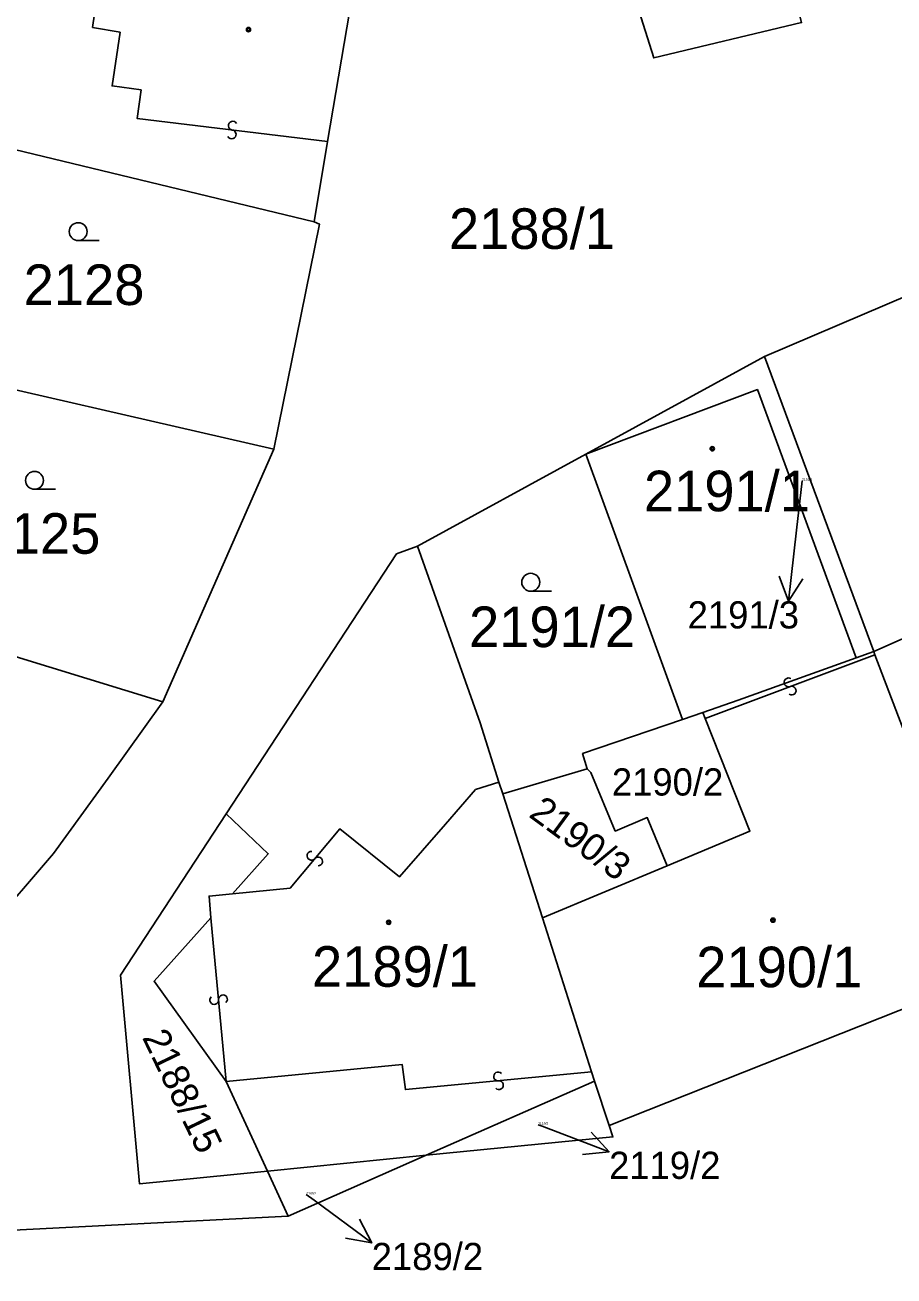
# Model space of a CAD drawing. Extents: x -596024 to -594475, y -1163820 to -1161957.
# Drawn here: x -595981.6 to -595945.3, y -1163000.7 to -1162948.3 of the extents above; entities that cross this region are included whole.
import ezdxf

# ---------------------------------------------------------------- set-up
doc = ezdxf.new("R2010")
doc.units = 0
for name, color, linetype in [('Level 1', 7, 'Continuous'), ('Level 13', 7, 'Continuous'), ('Level 3', 7, 'Continuous'), ('Level 4', 7, 'Continuous'), ('Level 5', 7, 'Continuous'), ('Level 57', 7, 'Continuous'), ('Level 60', 7, 'Continuous')]:
    doc.layers.add(name, color=color, linetype=linetype)

msp = doc.modelspace()

# ---------------------------------------------------------------- linework, layer by layer
at = {"layer": 'Level 1'}
for points in [[(-595968.97, -1162953.21), (-595967.57, -1162944.98)], [(-595956.2, -1162946.87), (-595955.31, -1162949.71), (-595949.12, -1162948.23)], [(-595969.53, -1162956.57), (-595989.38, -1162951.78)], [(-595969.53, -1162956.57), (-595968.97, -1162953.21)], [(-595950.67, -1162962.21), (-595942.49, -1162958.73), (-595931.21, -1162955.02)], [(-595971.22, -1162966.1), (-595969.31, -1162956.67), (-595969.53, -1162956.57)], [(-595971.22, -1162966.1), (-595986.91, -1162962.5)], [(-595958.16, -1162966.31), (-595950.67, -1162962.21)], [(-595950.67, -1162962.21), (-595946.1, -1162974.57)], [(-595958.16, -1162966.31), (-595950.97, -1162963.6), (-595946.84, -1162974.84)], [(-595975.86, -1162976.69), (-595971.22, -1162966.1)], [(-595965.2, -1162970.16), (-595958.16, -1162966.31)], [(-595954.11, -1162977.42), (-595958.16, -1162966.31)], [(-595934.03, -1162966.89), (-595938.96, -1162968.52), (-595938.13, -1162971.04), (-595946.1, -1162974.57)], [(-595965.2, -1162970.16), (-595966.08, -1162970.49), (-595973.22, -1162981.38)], [(-595965.2, -1162970.16), (-595962.58, -1162977.57), (-595961.79, -1162980.05)], [(-595975.86, -1162976.69), (-595990.39, -1162972.23)], [(-595946.1, -1162974.57), (-595946.84, -1162974.84)], [(-595946.1, -1162974.57), (-595946.05, -1162974.71)], [(-595946.05, -1162974.71), (-595943.52, -1162981.33)], [(-595953.25, -1162977.13), (-595951.77, -1162976.62), (-595946.84, -1162974.84)], [(-595983.23, -1162986.27), (-595980.45, -1162983.04), (-595978.15, -1162979.88), (-595975.86, -1162976.69)], [(-595953.25, -1162977.13), (-595954.11, -1162977.42)], [(-595953.15, -1162977.38), (-595953.25, -1162977.13)], [(-595954.11, -1162977.42), (-595958.29, -1162978.85), (-595958.1, -1162979.49)], [(-595954.75, -1162983.55), (-595951.28, -1162982.1), (-595953.15, -1162977.38)], [(-595958.1, -1162979.49), (-595961.63, -1162980.54)], [(-595954.75, -1162983.55), (-595955.58, -1162981.53), (-595956.92, -1162982.1), (-595957.94, -1162979.65), (-595958.1, -1162979.49)], [(-595961.79, -1162980.05), (-595961.63, -1162980.54)], [(-595959.97, -1162985.73), (-595961.63, -1162980.54)], [(-595971.49, -1162996.34), (-595976.85, -1162996.87), (-595977.64, -1162988.13), (-595973.22, -1162981.38)], [(-595973.22, -1162981.38), (-595971.45, -1162983.05), (-595972.95, -1162984.72)], [(-595959.97, -1162985.73), (-595954.75, -1162983.55)], [(-595972.95, -1162984.72), (-595973.93, -1162984.82), (-595973.85, -1162985.73)], [(-595973.85, -1162985.73), (-595976.23, -1162988.39), (-595973.21, -1162992.59)], [(-595957.92, -1162992.18), (-595959.97, -1162985.73)], [(-595957.18, -1162994.43), (-595940.98, -1162988.01)], [(-595957.92, -1162992.18), (-595957.79, -1162992.58)], [(-595971.49, -1162996.34), (-595973.21, -1162992.59)], [(-595964.84, -1162995.68), (-595957.79, -1162992.58)], [(-595957.79, -1162992.58), (-595957.18, -1162994.43)], [(-595964.84, -1162995.68), (-595957.02, -1162994.91), (-595957.18, -1162994.43)], [(-595964.84, -1162995.68), (-595971.49, -1162996.34)], [(-595970.62, -1162998.23), (-595964.84, -1162995.68)], [(-595970.62, -1162998.23), (-595971.49, -1162996.34)], [(-595970.62, -1162998.23), (-595993.35, -1162999.39)]]:
    msp.add_lwpolyline(points, dxfattribs=at)
at = {"layer": 'Level 13'}
for centre, start, end in [((-595972.937, -1162952.547), 30.29, 262.88), ((-595972.984, -1162952.913), 210.5045, 82.6024), ((-595949.663, -1162975.867), 57.9818, 290.0798), ((-595949.536, -1162976.213), 237.7674, 110.3574), ((-595969.641, -1162983.131), 87.1714, 319.7614), ((-595969.36, -1162983.37), 267.3858, 139.4838), ((-595973.714, -1162989.175), 132.7027, 4.8007), ((-595973.347, -1162989.144), 312.4882, 185.0782), ((-595961.826, -1162992.376), 42.8721, 274.9701), ((-595961.793, -1162992.743), 222.6576, 95.2476)]:
    msp.add_arc(centre, 0.184, start, end, dxfattribs=at)
at = {"layer": 'Level 3'}
for points in [[(-595968.97, -1162953.21), (-595976.94, -1162952.25), (-595976.78, -1162951.05), (-595977.99, -1162950.88), (-595977.66, -1162948.63), (-595978.81, -1162948.43), (-595978.63, -1162947.18), (-595978.79, -1162947.15), (-595978.24, -1162943.41)], [(-595953.15, -1162977.38), (-595946.05, -1162974.71)], [(-595961.79, -1162980.05), (-595962.77, -1162980.35), (-595964.03, -1162981.81), (-595965.96, -1162984.02), (-595968.46, -1162982.01), (-595970.54, -1162984.49), (-595972.95, -1162984.72)], [(-595973.21, -1162992.59), (-595973.85, -1162985.73)], [(-595973.21, -1162992.59), (-595965.85, -1162991.87), (-595965.71, -1162992.93), (-595957.92, -1162992.18)]]:
    msp.add_lwpolyline(points, dxfattribs=at)
at = {"layer": 'Level 5'}
for p, q in [((-595979.41, -1162957.36), (-595978.535, -1162957.36)), ((-595981.24, -1162967.78), (-595980.365, -1162967.78)), ((-595960.46, -1162972.05), (-595959.585, -1162972.05))]:
    msp.add_line(p, q, dxfattribs=at)
for centre, radius in [((-595972.28, -1162948.52), 0.09), ((-595972.28, -1162948.52), 0.0521), ((-595979.41, -1162956.985), 0.375), ((-595952.86, -1162966.08), 0.09), ((-595952.86, -1162966.08), 0.0521), ((-595981.24, -1162967.405), 0.375), ((-595960.46, -1162971.675), 0.375), ((-595966.41, -1162985.92), 0.09), ((-595966.41, -1162985.92), 0.0521), ((-595950.32, -1162985.83), 0.09), ((-595950.32, -1162985.83), 0.0521)]:
    msp.add_circle(centre, radius, dxfattribs=at)
at = {"layer": 'Level 57'}
for p, q in [((-595949.1, -1162967.42), (-595949.334, -1162969.489)), ((-595949.334, -1162969.489), (-595949.67, -1162972.47)), ((-595960.15, -1162994.4), (-595959.984, -1162994.463)), ((-595959.984, -1162994.463), (-595957.18, -1162995.53)), ((-595969.86, -1162997.32), (-595969.531, -1162997.564)), ((-595969.531, -1162997.564), (-595967.12, -1162999.35))]:
    msp.add_line(p, q, dxfattribs=at)
for points in [[(-595949.061, -1162971.532), (-595949.67, -1162972.47), (-595950.055, -1162971.42)], [(-595957.937, -1162994.707), (-595957.18, -1162995.53), (-595958.293, -1162995.642)], [(-595967.626, -1162998.353), (-595967.12, -1162999.35), (-595968.222, -1162999.156)]]:
    msp.add_lwpolyline(points, dxfattribs=at)
at = {"layer": 'Level 60'}
for points in [[(-595958.99, -1162933.23), (-595959.54, -1162929.94), (-595959.64, -1162928.73), (-595960.71, -1162916.38), (-595954.47, -1162915.56), (-595953.88, -1162923.87), (-595953.69, -1162926.6), (-595953.39, -1162928.83), (-595953.31, -1162929.42), (-595952.98, -1162931.95), (-595953.08, -1162932.3), (-595953.68, -1162935.69), (-595952.71, -1162938.94), (-595950.92, -1162938.63), (-595949.84, -1162945.38), (-595949.12, -1162948.23), (-595955.31, -1162949.71), (-595956.2, -1162946.87)], [(-596009.19, -1162949.12), (-596012.98, -1162948.44), (-596011.05, -1162938.75), (-596007.41, -1162939.32), (-596001.3, -1162940.16), (-595998.35, -1162940.53), (-595996.92, -1162940.71), (-595990.45, -1162941.67), (-595987.96, -1162942), (-595987.61, -1162942.05), (-595978.24, -1162943.41), (-595974.47, -1162943.95), (-595967.57, -1162944.98), (-595968.97, -1162953.21), (-595969.53, -1162956.57), (-595989.38, -1162951.78), (-595989.67, -1162951.71), (-595991.62, -1162951.35), (-595992.41, -1162951.21), (-595994.23, -1162950.96), (-595997.62, -1162950.49), (-595998.08, -1162950.45), (-596000.25, -1162950.27)], [(-595969.31, -1162956.67), (-595971.22, -1162966.1), (-595986.91, -1162962.5), (-595986.37, -1162959.04), (-595990.65, -1162958.26), (-595990.15, -1162955.34), (-595989.85, -1162955.39), (-595989.38, -1162951.78), (-595969.53, -1162956.57)], [(-595950.67, -1162962.21), (-595942.49, -1162958.73), (-595931.21, -1162955.02), (-595929.93, -1162958.74), (-595927.84, -1162964.62), (-595934.03, -1162966.89), (-595938.96, -1162968.52), (-595938.13, -1162971.04), (-595946.1, -1162974.57)], [(-595975.86, -1162976.69), (-595990.39, -1162972.23), (-595992.62, -1162971.72), (-595991.84, -1162968.06), (-595991.58, -1162966.83), (-595987.82, -1162967.36), (-595986.91, -1162962.5), (-595971.22, -1162966.1)], [(-595950.97, -1162963.6), (-595958.16, -1162966.31), (-595950.67, -1162962.21), (-595946.1, -1162974.57), (-595946.84, -1162974.84)], [(-595951.77, -1162976.62), (-595953.25, -1162977.13), (-595954.11, -1162977.42), (-595958.16, -1162966.31), (-595950.97, -1162963.6), (-595946.84, -1162974.84)], [(-595940.18, -1162989.98), (-595940.98, -1162988.01), (-595943.52, -1162981.33), (-595946.05, -1162974.71), (-595946.1, -1162974.57), (-595938.13, -1162971.04), (-595938.96, -1162968.52), (-595934.03, -1162966.89), (-595927.84, -1162964.62), (-595923.34, -1162978.02), (-595921.07, -1162984.8)], [(-595958.16, -1162966.31), (-595954.11, -1162977.42), (-595958.29, -1162978.85), (-595958.1, -1162979.49), (-595961.63, -1162980.54), (-595961.79, -1162980.05), (-595962.58, -1162977.57), (-595965.2, -1162970.16)], [(-595973.93, -1162984.82), (-595972.95, -1162984.72), (-595971.45, -1162983.05), (-595973.22, -1162981.38), (-595966.08, -1162970.49), (-595965.2, -1162970.16), (-595962.58, -1162977.57), (-595961.79, -1162980.05), (-595961.63, -1162980.54), (-595959.97, -1162985.73), (-595957.92, -1162992.18), (-595957.79, -1162992.58), (-595964.84, -1162995.68), (-595971.49, -1162996.34), (-595973.21, -1162992.59), (-595976.23, -1162988.39), (-595973.85, -1162985.73)], [(-595978.15, -1162979.88), (-595980.45, -1162983.04), (-595983.23, -1162986.27), (-595991.9, -1162981.05), (-595991.18, -1162976.32), (-595990.39, -1162972.23), (-595975.86, -1162976.69)], [(-595959.97, -1162985.73), (-595954.75, -1162983.55), (-595951.28, -1162982.1), (-595953.15, -1162977.38), (-595953.25, -1162977.13), (-595951.77, -1162976.62), (-595946.84, -1162974.84), (-595946.1, -1162974.57), (-595946.05, -1162974.71), (-595943.52, -1162981.33), (-595940.98, -1162988.01), (-595957.18, -1162994.43), (-595957.79, -1162992.58), (-595957.92, -1162992.18)], [(-595954.75, -1162983.55), (-595955.58, -1162981.53), (-595956.92, -1162982.1), (-595957.94, -1162979.65), (-595958.1, -1162979.49), (-595958.29, -1162978.85), (-595954.11, -1162977.42), (-595953.25, -1162977.13), (-595953.15, -1162977.38), (-595951.28, -1162982.1)], [(-595954.75, -1162983.55), (-595959.97, -1162985.73), (-595961.63, -1162980.54), (-595958.1, -1162979.49), (-595957.94, -1162979.65), (-595956.92, -1162982.1), (-595955.58, -1162981.53)], [(-595972.95, -1162984.72), (-595973.93, -1162984.82), (-595973.85, -1162985.73), (-595976.23, -1162988.39), (-595973.21, -1162992.59), (-595971.49, -1162996.34), (-595976.85, -1162996.87), (-595977.64, -1162988.13), (-595973.22, -1162981.38), (-595971.45, -1162983.05)], [(-595957.02, -1162994.91), (-595964.84, -1162995.68), (-595957.79, -1162992.58), (-595957.18, -1162994.43)], [(-595971.49, -1162996.34), (-595964.84, -1162995.68), (-595970.62, -1162998.23)]]:
    msp.add_lwpolyline(points, close=True, dxfattribs=at)
for points in [[(-595942.49, -1162958.73), (-595950.67, -1162962.21), (-595958.16, -1162966.31), (-595965.2, -1162970.16), (-595966.08, -1162970.49), (-595973.22, -1162981.38), (-595977.64, -1162988.13), (-595976.85, -1162996.87), (-595971.49, -1162996.34), (-595970.62, -1162998.23), (-595993.35, -1162999.39), (-595990.19, -1162995.21), (-595986.92, -1162990.89), (-595984.86, -1162988.16), (-595983.23, -1162986.27), (-595980.45, -1162983.04), (-595978.15, -1162979.88), (-595975.86, -1162976.69), (-595971.22, -1162966.1), (-595969.31, -1162956.67), (-595969.53, -1162956.57), (-595968.97, -1162953.21), (-595967.57, -1162944.98)], [(-595956.2, -1162946.87), (-595955.31, -1162949.71), (-595949.12, -1162948.23)], [(-596013.91, -1163035.64), (-596013, -1163034.5), (-596010.5, -1163034.1), (-596013, -1163011.8), (-596015.2, -1163011), (-596016.1, -1163009.9), (-596016.6, -1163005.6), (-596015.7, -1163003.7), (-596014.2, -1163003.3), (-596001.88, -1163004.81), (-596000.63, -1162997.03), (-595993.35, -1162999.39), (-595970.62, -1162998.23), (-595964.84, -1162995.68), (-595957.02, -1162994.91), (-595957.18, -1162994.43), (-595940.98, -1162988.01), (-595940.18, -1162989.98), (-595921.07, -1162984.8), (-595917.43, -1162983.88), (-595907.57, -1162981.5), (-595906.63, -1162985.26), (-595898.87, -1162983.32)]]:
    msp.add_lwpolyline(points, dxfattribs=at)

# ---------------------------------------------------------------- texts
at = {"layer": 'Level 4'}
for s, height, p in [('2188/1', 1.7, (-595963.885, -1162957.71)), ('2128', 1.7, (-595981.693, -1162960.06)), ('2191/1', 1.7, (-595955.721, -1162968.7)), ('2191/3', 0.1, (-595949.1, -1162967.42)), ('2125', 1.7, (-595983.54, -1162970.48)), ('2191/2', 1.7, (-595963.043, -1162974.39)), ('2190/2', 1.14, (-595957.063, -1162980.61)), ('2189/1', 1.7, (-595969.62, -1162988.62)), ('2190/1', 1.7, (-595953.532, -1162988.64)), ('2119/2', 0.1, (-595960.15, -1162994.4)), ('2189/2', 0.1, (-595969.86, -1162997.32))]:
    msp.add_text(s, height=height, dxfattribs=at).set_placement(p)
for s, rotation, p in [('2190/3', 323.7349, (-595960.589, -1162981.471)), ('2188/15', 295.7635, (-595976.75, -1162990.74))]:
    msp.add_text(s, height=1.14, rotation=rotation, dxfattribs=at).set_placement(p)
at = {"layer": 'Level 57'}
for s, p in [('2191/3', (-595953.89, -1162973.61)), ('2119/2', (-595957.18, -1162996.67)), ('2189/2', (-595967.12, -1163000.49))]:
    msp.add_text(s, height=1.14, dxfattribs=at).set_placement(p)

doc.saveas('drawing.dxf')
